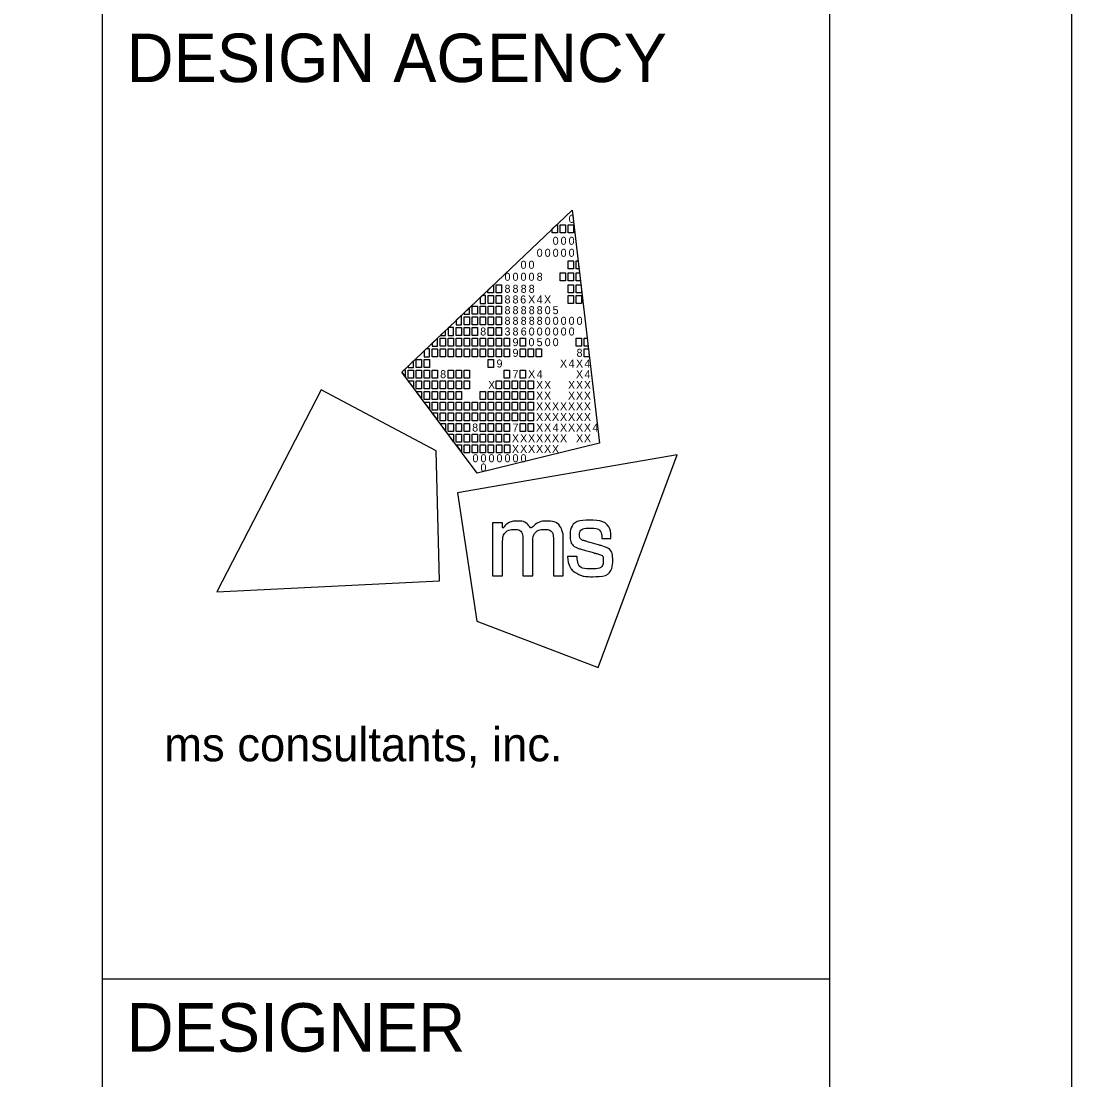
# Model space of a CAD drawing. Extents: x -0.7 to 34, y 0 to 22.
# Drawn here: x 31.832 to 34, y 2.292 to 4.476 of the extents above; entities that cross this region are included whole.
import ezdxf

# ---------------------------------------------------------------- set-up
doc = ezdxf.new("R2010")
doc.units = 0
for name, color, linetype in [('Default', 7, 'Continuous'), ('SH_Border', 7, 'Continuous'), ('SH_Cut_Line', 7, 'Continuous'), ('SH_Data', 7, 'Continuous')]:
    doc.layers.add(name, color=color, linetype=linetype)

msp = doc.modelspace()

# ---------------------------------------------------------------- linework, layer by layer
at = {"layer": 'Default'}
for p, q in [((32.6175, 3.7519), (32.9688, 4.0861)), ((32.9688, 4.0861), (32.9688, 4.0861)), ((32.9688, 4.0861), (33.0253, 3.6052)), ((32.773, 3.543), (32.6175, 3.7519)), ((33.0253, 3.6052), (32.773, 3.543))]:
    msp.add_line(p, q, dxfattribs=at)
for points in [[(32.9279, 4.0472), (32.9369, 4.0558), (32.9389, 4.0558), (32.9389, 4.0393), (32.9279, 4.0393)], [(32.9444, 4.0558), (32.9554, 4.0558), (32.9554, 4.0393), (32.9444, 4.0393)], [(32.9609, 4.0558), (32.9719, 4.0558), (32.9719, 4.0393), (32.9609, 4.0393)], [(32.9606, 3.9815), (32.9716, 3.9815), (32.9716, 3.965), (32.9606, 3.965)], [(32.9771, 3.9815), (32.9811, 3.9815), (32.983, 3.965), (32.9771, 3.965)], [(32.9441, 3.9567), (32.9551, 3.9567), (32.9551, 3.9402), (32.9441, 3.9402)], [(32.9606, 3.9567), (32.9716, 3.9567), (32.9716, 3.9402), (32.9606, 3.9402)], [(32.9771, 3.9567), (32.984, 3.9567), (32.9859, 3.9402), (32.9771, 3.9402)], [(32.7953, 3.9211), (32.8064, 3.9316), (32.8064, 3.9154), (32.7953, 3.9154)], [(32.8123, 3.9319), (32.8233, 3.9319), (32.8233, 3.9154), (32.8123, 3.9154)], [(32.9606, 3.9319), (32.9716, 3.9319), (32.9716, 3.9154), (32.9606, 3.9154)], [(32.9771, 3.9319), (32.9869, 3.9319), (32.9881, 3.9218), (32.9881, 3.9154), (32.9771, 3.9154)], [(32.7958, 3.9099), (32.8068, 3.9099), (32.8068, 3.8934), (32.7958, 3.8934)], [(32.8123, 3.9099), (32.8233, 3.9099), (32.8233, 3.8934), (32.8123, 3.8934)], [(32.9606, 3.9099), (32.9716, 3.9099), (32.9716, 3.8934), (32.9606, 3.8934)], [(32.9771, 3.9099), (32.9881, 3.9099), (32.9881, 3.8934), (32.9771, 3.8934)], [(32.7627, 3.8879), (32.7737, 3.8879), (32.7737, 3.8714), (32.7627, 3.8714)], [(32.7793, 3.8879), (32.7903, 3.8879), (32.7903, 3.8714), (32.7793, 3.8714)], [(32.7958, 3.8879), (32.8068, 3.8879), (32.8068, 3.8714), (32.7958, 3.8714)], [(32.8123, 3.8879), (32.8233, 3.8879), (32.8233, 3.8714), (32.8123, 3.8714)], [(32.7462, 3.8659), (32.7572, 3.8659), (32.7572, 3.8494), (32.7462, 3.8494)], [(32.7627, 3.8659), (32.7737, 3.8659), (32.7737, 3.8494), (32.7627, 3.8494)], [(32.7793, 3.8659), (32.7903, 3.8659), (32.7903, 3.8494), (32.7793, 3.8494)], [(32.7958, 3.8659), (32.8068, 3.8659), (32.8068, 3.8494), (32.7958, 3.8494)], [(32.8123, 3.8659), (32.8233, 3.8659), (32.8233, 3.8494), (32.8123, 3.8494)], [(32.7297, 3.8439), (32.7407, 3.8439), (32.7407, 3.8273), (32.7297, 3.8273)], [(32.7462, 3.8439), (32.7572, 3.8439), (32.7572, 3.8273), (32.7462, 3.8273)], [(32.7627, 3.8439), (32.7737, 3.8439), (32.7737, 3.8273), (32.7627, 3.8273)], [(32.7958, 3.8439), (32.8068, 3.8439), (32.8068, 3.8273), (32.7958, 3.8273)], [(32.8123, 3.8439), (32.8233, 3.8439), (32.8233, 3.8273), (32.8123, 3.8273)], [(32.6967, 3.8218), (32.7077, 3.8218), (32.7077, 3.8053), (32.6967, 3.8053)], [(32.7132, 3.8218), (32.7242, 3.8218), (32.7242, 3.8053), (32.7132, 3.8053)], [(32.7297, 3.8218), (32.7407, 3.8218), (32.7407, 3.8053), (32.7297, 3.8053)], [(32.7462, 3.8218), (32.7572, 3.8218), (32.7572, 3.8053), (32.7462, 3.8053)], [(32.7627, 3.8218), (32.7737, 3.8218), (32.7737, 3.8053), (32.7627, 3.8053)], [(32.7793, 3.8218), (32.7903, 3.8218), (32.7903, 3.8053), (32.7793, 3.8053)], [(32.7958, 3.8218), (32.8068, 3.8218), (32.8068, 3.8053), (32.7958, 3.8053)], [(32.8123, 3.8218), (32.8233, 3.8218), (32.8233, 3.8053), (32.8123, 3.8053)], [(32.8288, 3.8218), (32.8398, 3.8218), (32.8398, 3.8053), (32.8288, 3.8053)], [(32.8618, 3.8218), (32.8728, 3.8218), (32.8728, 3.8053), (32.8618, 3.8053)], [(32.9771, 3.8218), (32.9881, 3.8218), (32.9881, 3.8053), (32.9771, 3.8053)], [(32.9935, 3.8218), (32.9998, 3.8218), (33.0018, 3.8053), (32.9935, 3.8053)], [(32.6802, 3.7998), (32.6912, 3.7998), (32.6912, 3.7833), (32.6802, 3.7833)], [(32.6967, 3.7998), (32.7077, 3.7998), (32.7077, 3.7833), (32.6967, 3.7833)], [(32.7132, 3.7998), (32.7242, 3.7998), (32.7242, 3.7833), (32.7132, 3.7833)], [(32.7297, 3.7998), (32.7407, 3.7998), (32.7407, 3.7833), (32.7297, 3.7833)], [(32.7462, 3.7998), (32.7572, 3.7998), (32.7572, 3.7833), (32.7462, 3.7833)], [(32.7627, 3.7998), (32.7737, 3.7998), (32.7737, 3.7833), (32.7627, 3.7833)], [(32.7793, 3.7998), (32.7903, 3.7998), (32.7903, 3.7833), (32.7793, 3.7833)], [(32.7958, 3.7998), (32.8068, 3.7998), (32.8068, 3.7833), (32.7958, 3.7833)], [(32.8123, 3.7998), (32.8233, 3.7998), (32.8233, 3.7833), (32.8123, 3.7833)], [(32.8288, 3.7998), (32.8398, 3.7998), (32.8398, 3.7833), (32.8288, 3.7833)], [(32.8618, 3.7998), (32.8728, 3.7998), (32.8728, 3.7833), (32.8618, 3.7833)], [(32.8783, 3.7998), (32.8893, 3.7998), (32.8893, 3.7833), (32.8783, 3.7833)], [(32.8947, 3.7998), (32.9057, 3.7998), (32.9057, 3.7833), (32.8947, 3.7833)], [(32.9935, 3.7998), (33.0024, 3.7998), (33.0044, 3.7833), (32.9935, 3.7833)], [(32.6471, 3.7778), (32.6581, 3.7778), (32.6581, 3.7613), (32.6471, 3.7613)], [(32.6637, 3.7778), (32.6747, 3.7778), (32.6747, 3.7613), (32.6637, 3.7613)], [(32.7958, 3.7778), (32.8068, 3.7778), (32.8068, 3.7613), (32.7958, 3.7613)], [(32.6306, 3.7558), (32.6416, 3.7558), (32.6416, 3.7393), (32.6306, 3.7393)], [(32.6471, 3.7558), (32.6581, 3.7558), (32.6581, 3.7393), (32.6471, 3.7393)], [(32.6637, 3.7558), (32.6747, 3.7558), (32.6747, 3.7393), (32.6637, 3.7393)], [(32.6802, 3.7558), (32.6912, 3.7558), (32.6912, 3.7393), (32.6802, 3.7393)], [(32.7132, 3.7558), (32.7242, 3.7558), (32.7242, 3.7393), (32.7132, 3.7393)], [(32.7297, 3.7558), (32.7407, 3.7558), (32.7407, 3.7393), (32.7297, 3.7393)], [(32.7462, 3.7558), (32.7572, 3.7558), (32.7572, 3.7393), (32.7462, 3.7393)], [(32.8288, 3.7558), (32.8398, 3.7558), (32.8398, 3.7393), (32.8288, 3.7393)], [(32.8618, 3.7558), (32.8728, 3.7558), (32.8728, 3.7393), (32.8618, 3.7393)], [(32.6306, 3.7338), (32.6416, 3.7338), (32.6416, 3.72)], [(32.6471, 3.7338), (32.6581, 3.7338), (32.6581, 3.7173), (32.6471, 3.7173)], [(32.6637, 3.7338), (32.6747, 3.7338), (32.6747, 3.7173), (32.6637, 3.7173)], [(32.6802, 3.7338), (32.6912, 3.7338), (32.6912, 3.7173), (32.6802, 3.7173)], [(32.6967, 3.7338), (32.7077, 3.7338), (32.7077, 3.7173), (32.6967, 3.7173)], [(32.7132, 3.7338), (32.7242, 3.7338), (32.7242, 3.7173), (32.7132, 3.7173)], [(32.7297, 3.7338), (32.7407, 3.7338), (32.7407, 3.7173), (32.7297, 3.7173)], [(32.7462, 3.7338), (32.7572, 3.7338), (32.7572, 3.7173), (32.7462, 3.7173)], [(32.8123, 3.7338), (32.8233, 3.7338), (32.8233, 3.7173), (32.8123, 3.7173)], [(32.8288, 3.7338), (32.8398, 3.7338), (32.8398, 3.7173), (32.8288, 3.7173)], [(32.8453, 3.7338), (32.8563, 3.7338), (32.8563, 3.7173), (32.8453, 3.7173)], [(32.8618, 3.7338), (32.8728, 3.7338), (32.8728, 3.7173), (32.8618, 3.7173)], [(32.8783, 3.7338), (32.8893, 3.7338), (32.8893, 3.7173), (32.8783, 3.7173)], [(32.6471, 3.7117), (32.6581, 3.7117), (32.6581, 3.698)], [(32.6637, 3.7117), (32.6747, 3.7117), (32.6747, 3.6952), (32.6637, 3.6952)], [(32.6802, 3.7117), (32.6912, 3.7117), (32.6912, 3.6952), (32.6802, 3.6952)], [(32.6967, 3.7117), (32.7077, 3.7117), (32.7077, 3.6952), (32.6967, 3.6952)], [(32.7132, 3.7117), (32.7242, 3.7117), (32.7242, 3.6952), (32.7132, 3.6952)], [(32.7297, 3.7117), (32.7407, 3.7117), (32.7407, 3.6952), (32.7297, 3.6952)], [(32.7793, 3.7117), (32.7903, 3.7117), (32.7903, 3.6952), (32.7793, 3.6952)], [(32.7958, 3.7117), (32.8068, 3.7117), (32.8068, 3.6952), (32.7958, 3.6952)], [(32.8123, 3.7117), (32.8233, 3.7117), (32.8233, 3.6952), (32.8123, 3.6952)], [(32.8288, 3.7117), (32.8398, 3.7117), (32.8398, 3.6952), (32.8288, 3.6952)], [(32.8453, 3.7117), (32.8563, 3.7117), (32.8563, 3.6952), (32.8453, 3.6952)], [(32.8618, 3.7117), (32.8728, 3.7117), (32.8728, 3.6952), (32.8618, 3.6952)], [(32.8783, 3.7117), (32.8893, 3.7117), (32.8893, 3.6952), (32.8783, 3.6952)], [(32.6637, 3.6897), (32.6747, 3.6897), (32.6747, 3.676)], [(32.6747, 3.6897), (32.6747, 3.6897), (32.6747, 3.6897)], [(32.6802, 3.6897), (32.6912, 3.6897), (32.6912, 3.6732), (32.6802, 3.6732)], [(32.6967, 3.6897), (32.7077, 3.6897), (32.7077, 3.6732), (32.6967, 3.6732)], [(32.7132, 3.6897), (32.7242, 3.6897), (32.7242, 3.6732), (32.7132, 3.6732)], [(32.7297, 3.6897), (32.7407, 3.6897), (32.7407, 3.6732), (32.7297, 3.6732)], [(32.7462, 3.6897), (32.7572, 3.6897), (32.7572, 3.6732), (32.7462, 3.6732)], [(32.7627, 3.6897), (32.7737, 3.6897), (32.7737, 3.6732), (32.7627, 3.6732)], [(32.7793, 3.6897), (32.7903, 3.6897), (32.7903, 3.6732), (32.7793, 3.6732)], [(32.7958, 3.6897), (32.8068, 3.6897), (32.8068, 3.6732), (32.7958, 3.6732)], [(32.8123, 3.6897), (32.8233, 3.6897), (32.8233, 3.6732), (32.8123, 3.6732)], [(32.8288, 3.6897), (32.8398, 3.6897), (32.8398, 3.6732), (32.8288, 3.6732)], [(32.8453, 3.6897), (32.8563, 3.6897), (32.8563, 3.6732), (32.8453, 3.6732)], [(32.8618, 3.6897), (32.8728, 3.6897), (32.8728, 3.6732), (32.8618, 3.6732)], [(32.8783, 3.6897), (32.8893, 3.6897), (32.8893, 3.6732), (32.8783, 3.6732)], [(32.6802, 3.6677), (32.6912, 3.6677), (32.6912, 3.654)], [(32.6967, 3.6677), (32.7077, 3.6677), (32.7077, 3.6512), (32.6967, 3.6512)], [(32.7132, 3.6677), (32.7242, 3.6677), (32.7242, 3.6512), (32.7132, 3.6512)], [(32.7297, 3.6677), (32.7407, 3.6677), (32.7407, 3.6512), (32.7297, 3.6512)], [(32.7462, 3.6677), (32.7572, 3.6677), (32.7572, 3.6512), (32.7462, 3.6512)], [(32.7627, 3.6677), (32.7737, 3.6677), (32.7737, 3.6512), (32.7627, 3.6512)], [(32.7793, 3.6677), (32.7903, 3.6677), (32.7903, 3.6512), (32.7793, 3.6512)], [(32.7958, 3.6677), (32.8068, 3.6677), (32.8068, 3.6512), (32.7958, 3.6512)], [(32.8123, 3.6677), (32.8233, 3.6677), (32.8233, 3.6512), (32.8123, 3.6512)], [(32.8288, 3.6677), (32.8398, 3.6677), (32.8398, 3.6512), (32.8288, 3.6512)], [(32.8453, 3.6677), (32.8563, 3.6677), (32.8563, 3.6512), (32.8453, 3.6512)], [(32.8618, 3.6677), (32.8728, 3.6677), (32.8728, 3.6512), (32.8618, 3.6512)], [(32.8783, 3.6677), (32.8893, 3.6677), (32.8893, 3.6512), (32.8783, 3.6512)], [(32.7077, 3.6305), (32.6965, 3.6457), (32.7077, 3.6457)], [(32.7132, 3.6457), (32.7242, 3.6457), (32.7242, 3.6292), (32.7132, 3.6292)], [(32.7297, 3.6457), (32.7407, 3.6457), (32.7407, 3.6292), (32.7297, 3.6292)], [(32.7462, 3.6457), (32.7572, 3.6457), (32.7572, 3.6292), (32.7462, 3.6292)], [(32.7793, 3.6457), (32.7903, 3.6457), (32.7903, 3.6292), (32.7793, 3.6292)], [(32.7958, 3.6457), (32.8068, 3.6457), (32.8068, 3.6292), (32.7958, 3.6292)], [(32.8123, 3.6457), (32.8233, 3.6457), (32.8233, 3.6292), (32.8123, 3.6292)], [(32.8288, 3.6457), (32.8398, 3.6457), (32.8398, 3.6292), (32.8288, 3.6292)], [(32.8618, 3.6457), (32.8728, 3.6457), (32.8728, 3.6292), (32.8618, 3.6292)], [(32.8783, 3.6457), (32.8893, 3.6457), (32.8893, 3.6292), (32.8783, 3.6292)], [(32.724, 3.6082), (32.7132, 3.6237), (32.7242, 3.6237)], [(32.7297, 3.6237), (32.7407, 3.6237), (32.7407, 3.6072), (32.7297, 3.6072)], [(32.7462, 3.6237), (32.7572, 3.6237), (32.7572, 3.6072), (32.7462, 3.6072)], [(32.7627, 3.6237), (32.7737, 3.6237), (32.7737, 3.6072), (32.7627, 3.6072)], [(32.7793, 3.6237), (32.7903, 3.6237), (32.7903, 3.6072), (32.7793, 3.6072)], [(32.7958, 3.6237), (32.8068, 3.6237), (32.8068, 3.6072), (32.7958, 3.6072)], [(32.8123, 3.6237), (32.8233, 3.6237), (32.8233, 3.6072), (32.8123, 3.6072)], [(32.8288, 3.6237), (32.8398, 3.6237), (32.8398, 3.6072), (32.8288, 3.6072)], [(32.7302, 3.6017), (32.7407, 3.6017), (32.7408, 3.5875)], [(32.7463, 3.6017), (32.7573, 3.6017), (32.7573, 3.5852), (32.7463, 3.5852)], [(32.763, 3.6017), (32.774, 3.6017), (32.774, 3.5852), (32.763, 3.5852)], [(32.7794, 3.6017), (32.7904, 3.6017), (32.7904, 3.5852), (32.7794, 3.5852)], [(32.796, 3.6017), (32.807, 3.6017), (32.807, 3.5852), (32.796, 3.5852)], [(32.8129, 3.6017), (32.8239, 3.6017), (32.8239, 3.5851), (32.8129, 3.5851)], [(32.8296, 3.6017), (32.8406, 3.6017), (32.8406, 3.5851), (32.8296, 3.5851)]]:
    msp.add_lwpolyline(points, close=True, dxfattribs=at)
for points in [[(32.7903, 3.9099), (32.7836, 3.9099), (32.7793, 3.9058), (32.7793, 3.8934), (32.7903, 3.8934), (32.7903, 3.9099)], [(32.7407, 3.8691), (32.7297, 3.8587), (32.7297, 3.8494), (32.7407, 3.8494), (32.7407, 3.8691)], [(32.7572, 3.8849), (32.7462, 3.8744), (32.7462, 3.8714), (32.7572, 3.8714), (32.7572, 3.8849)], [(32.7242, 3.8439), (32.7141, 3.8439), (32.7132, 3.843), (32.7132, 3.8273), (32.7242, 3.8273), (32.7242, 3.8439)], [(32.6912, 3.822), (32.6802, 3.8115), (32.6802, 3.8053), (32.6912, 3.8053), (32.6912, 3.822)], [(32.7077, 3.8377), (32.6968, 3.8273), (32.7077, 3.8273), (32.7077, 3.8377)], [(32.6747, 3.7998), (32.6679, 3.7998), (32.6637, 3.7958), (32.6637, 3.7833), (32.6747, 3.7833), (32.6747, 3.7998)], [(32.6416, 3.7749), (32.6306, 3.7644), (32.6306, 3.7613), (32.6416, 3.7613), (32.6416, 3.7749)], [(32.6251, 3.7558), (32.6216, 3.7558), (32.6175, 3.7519), (32.6251, 3.7417), (32.6251, 3.7558)], [(32.4512, 3.7149), (32.2359, 3.2988), (32.6956, 3.3215), (32.6884, 3.5892), (32.4512, 3.7149)], [(33.0229, 3.1422), (33.1859, 3.5814), (32.7324, 3.5029), (32.7722, 3.2381), (33.0229, 3.1422)]]:
    msp.add_lwpolyline(points, dxfattribs=at)
for points in [[(32.8048, 3.3315), (32.8048, 3.3315), (32.8048, 3.4409), (32.8048, 3.4409), (32.8048, 3.4409), (32.8255, 3.4409), (32.8255, 3.4409), (32.8255, 3.4409), (32.8255, 3.4297), (32.8255, 3.4297), (32.8346, 3.4399), (32.8457, 3.4445), (32.8555, 3.4445), (32.8688, 3.4445), (32.8791, 3.4372), (32.8837, 3.4266), (32.8915, 3.4381), (32.905, 3.4446), (32.9166, 3.4446), (32.9325, 3.4446), (32.9451, 3.435), (32.9494, 3.4213), (32.9494, 3.4212), (32.9494, 3.4212), (32.9494, 3.4212), (32.9501, 3.419), (32.9506, 3.4172), (32.9506, 3.4071), (32.9506, 3.4071), (32.9506, 3.3314), (32.9506, 3.3314), (32.9506, 3.3314), (32.9303, 3.3314), (32.9303, 3.3314), (32.9303, 3.3314), (32.9303, 3.4048), (32.9303, 3.4048), (32.9303, 3.4201), (32.9219, 3.4274), (32.911, 3.4274), (32.8995, 3.4274), (32.8879, 3.4171), (32.8879, 3.4001), (32.8879, 3.4001), (32.8879, 3.3315), (32.8879, 3.3315), (32.8879, 3.3315), (32.8674, 3.3315), (32.8674, 3.3315), (32.8674, 3.3315), (32.8674, 3.4059), (32.8674, 3.4059), (32.8674, 3.4203), (32.8588, 3.4274), (32.8496, 3.4274), (32.8384, 3.4274), (32.8254, 3.417), (32.8254, 3.3962), (32.8254, 3.3962), (32.8254, 3.3315), (32.8254, 3.3315), (32.8254, 3.3315), (32.8048, 3.3315), (32.8048, 3.3315)], [(32.9595, 3.3709), (32.9595, 3.3709), (32.9595, 3.3717), (32.9595, 3.3717), (32.9595, 3.3717), (32.9603, 3.3717), (32.9603, 3.3717), (32.9603, 3.3717), (32.9783, 3.3717), (32.9783, 3.3717), (32.9783, 3.3717), (32.9789, 3.3717), (32.9789, 3.3717), (32.9789, 3.3717), (32.979, 3.371), (32.979, 3.371), (32.9803, 3.3554), (32.9887, 3.346), (33.009, 3.346), (33.0273, 3.346), (33.0333, 3.3554), (33.0333, 3.3631), (33.0333, 3.3732), (33.0256, 3.3758), (33.0175, 3.378), (33.0175, 3.378), (32.987, 3.3867), (32.987, 3.3867), (32.972, 3.3909), (32.9648, 3.4019), (32.9648, 3.4142), (32.9648, 3.4303), (32.9768, 3.4462), (33.0052, 3.4462), (33.0348, 3.4462), (33.0489, 3.4285), (33.0489, 3.4095), (33.0489, 3.4095), (33.0489, 3.4087), (33.0489, 3.4087), (33.0489, 3.4087), (33.0482, 3.4087), (33.0482, 3.4087), (33.0482, 3.4087), (33.0312, 3.4087), (33.0312, 3.4087), (33.0312, 3.4087), (33.0305, 3.4087), (33.0305, 3.4087), (33.0305, 3.4087), (33.0305, 3.4094), (33.0305, 3.4094), (33.0301, 3.4208), (33.0226, 3.43), (33.0056, 3.43), (32.9891, 3.43), (32.9843, 3.4218), (32.9843, 3.4157), (32.9843, 3.4108), (32.9869, 3.4059), (32.9959, 3.4033), (32.9959, 3.4033), (33.0255, 3.3948), (33.0255, 3.3948), (33.0462, 3.3889), (33.0527, 3.3777), (33.0527, 3.3639), (33.0527, 3.3462), (33.041, 3.3298), (33.0087, 3.3298), (32.9952, 3.3298), (32.9877, 3.3321), (32.9823, 3.3348), (32.969, 3.3414), (32.9609, 3.3536), (32.9595, 3.3709)]]:
    msp.add_open_spline(points, degree=3, dxfattribs=at)
at = {"layer": 'SH_Border'}
for p, q in [((32, 0.5), (32, 21.5)), ((32, 2.5), (33.5, 2.5))]:
    msp.add_line(p, q, dxfattribs=at)
msp.add_lwpolyline([(1.5, 21.5), (33.5, 21.5), (33.5, 0.5), (1.5, 0.5)], close=True, dxfattribs=at)
at = {"layer": 'SH_Cut_Line'}
msp.add_lwpolyline([(0, 0), (34, 0), (34, 22), (0, 22)], close=True, dxfattribs=at)
at = {"layer": 'SH_Data'}
msp.add_line((32.75, 3.5), (32.75, 3.5), dxfattribs=at)

# ---------------------------------------------------------------- texts
at = {"layer": 'Default'}
for s, p in [('0', (32.9617, 4.0597)), ('0', (32.9288, 4.0145)), ('0', (32.9452, 4.0145)), ('0', (32.9617, 4.0145)), ('0', (32.8958, 3.9897)), ('0', (32.9123, 3.9897)), ('0', (32.9288, 3.9897)), ('0', (32.9452, 3.9897)), ('0', (32.9617, 3.9897)), ('0', (32.8625, 3.965)), ('0', (32.879, 3.965)), ('0', (32.8295, 3.9402)), ('0', (32.846, 3.9402)), ('0', (32.8625, 3.9402)), ('0', (32.879, 3.9402)), ('8', (32.8958, 3.9402)), ('8', (32.8295, 3.9154)), ('8', (32.846, 3.9154)), ('8', (32.8628, 3.9154)), ('8', (32.8793, 3.9154)), ('8', (32.8295, 3.8934)), ('8', (32.846, 3.8934)), ('6', (32.8618, 3.8934)), ('X', (32.8781, 3.8934)), ('4', (32.8958, 3.8934)), ('X', (32.911, 3.8934)), ('8', (32.8295, 3.8713)), ('8', (32.846, 3.8713)), ('8', (32.8628, 3.8713)), ('8', (32.8794, 3.8713)), ('8', (32.8958, 3.8713)), ('0', (32.9123, 3.8713)), ('5', (32.9287, 3.8713)), ('8', (32.8295, 3.8494)), ('8', (32.846, 3.8494)), ('8', (32.8628, 3.8494)), ('8', (32.8794, 3.8494)), ('8', (32.8958, 3.8494)), ('0', (32.9123, 3.8494)), ('0', (32.9288, 3.8494)), ('0', (32.9452, 3.8494)), ('0', (32.9617, 3.8494)), ('0', (32.9782, 3.8494)), ('8', (32.7793, 3.8273)), ('3', (32.8295, 3.8273)), ('8', (32.846, 3.8273)), ('6', (32.8629, 3.8273)), ('0', (32.8793, 3.8273)), ('0', (32.8958, 3.8273)), ('0', (32.9123, 3.8273)), ('0', (32.9288, 3.8273)), ('0', (32.9452, 3.8273)), ('0', (32.9617, 3.8273)), ('9', (32.846, 3.8053)), ('0', (32.879, 3.8053)), ('5', (32.8957, 3.8053)), ('0', (32.9123, 3.8053)), ('0', (32.9288, 3.8053)), ('9', (32.846, 3.7833)), ('8', (32.9781, 3.7833)), ('9', (32.813, 3.7613)), ('X', (32.9439, 3.7613)), ('4', (32.9617, 3.7613)), ('X', (32.9769, 3.7613)), ('4', (32.9946, 3.7613)), ('8', (32.6967, 3.7393)), ('7', (32.846, 3.7393)), ('X', (32.8781, 3.7393)), ('4', (32.8958, 3.7393)), ('X', (32.9769, 3.7393)), ('4', (32.9946, 3.7393)), ('X', (32.7955, 3.7173)), ('X', (32.8945, 3.7173)), ('X', (32.911, 3.7173)), ('X', (32.9604, 3.7173)), ('X', (32.9769, 3.7173)), ('X', (32.9933, 3.7173)), ('X', (32.8945, 3.6952)), ('X', (32.911, 3.6952)), ('X', (32.9604, 3.6952)), ('X', (32.9769, 3.6952)), ('X', (32.9933, 3.6952)), ('X', (32.8945, 3.6732)), ('X', (32.911, 3.6732)), ('X', (32.9274, 3.6732)), ('X', (32.9439, 3.6732)), ('X', (32.9604, 3.6732)), ('X', (32.9769, 3.6732)), ('X', (32.9933, 3.6732)), ('X', (32.8945, 3.6512)), ('X', (32.911, 3.6512)), ('X', (32.9274, 3.6512)), ('X', (32.9439, 3.6512)), ('X', (32.9604, 3.6512)), ('X', (32.9769, 3.6512)), ('X', (32.9933, 3.6512)), ('8', (32.7627, 3.6292)), ('7', (32.846, 3.6292)), ('X', (32.8945, 3.6292)), ('X', (32.911, 3.6292)), ('4', (32.9288, 3.6292)), ('X', (32.9439, 3.6292)), ('X', (32.9604, 3.6292)), ('X', (32.9769, 3.6292)), ('X', (32.9933, 3.6292)), ('4', (33.0111, 3.6292)), ('X', (32.8447, 3.6072)), ('X', (32.8616, 3.6072)), ('X', (32.878, 3.6072)), ('X', (32.8945, 3.6072)), ('X', (32.911, 3.6072)), ('X', (32.9274, 3.6072)), ('X', (32.9439, 3.6072)), ('X', (32.9771, 3.6072)), ('X', (32.9933, 3.6072)), ('0', (32.7634, 3.5659)), ('0', (32.7799, 3.5659)), ('0', (32.7965, 3.5659)), ('0', (32.813, 3.5659)), ('0', (32.8295, 3.5659)), ('X', (32.8447, 3.5851)), ('0', (32.846, 3.5659)), ('X', (32.8616, 3.5851)), ('0', (32.8625, 3.5659)), ('X', (32.878, 3.5851)), ('X', (32.8945, 3.5851)), ('X', (32.911, 3.5851)), ('X', (32.9274, 3.5851)), ('0', (32.7799, 3.5467))]:
    msp.add_text(s, height=0.0165, rotation=360, dxfattribs=at).set_placement(p)
at = {"layer": 'SH_Border'}
msp.add_text('ms consultants, inc.', height=0.07, rotation=360, dxfattribs=at).set_placement((32.1273, 2.9489))
at = {"layer": 'SH_Data'}
for s, p in [('DESIGN AGENCY', (32.05, 4.35)), ('DESIGNER', (32.05, 2.35))]:
    msp.add_text(s, height=0.1, dxfattribs=at).set_placement(p)

doc.saveas('drawing.dxf')
